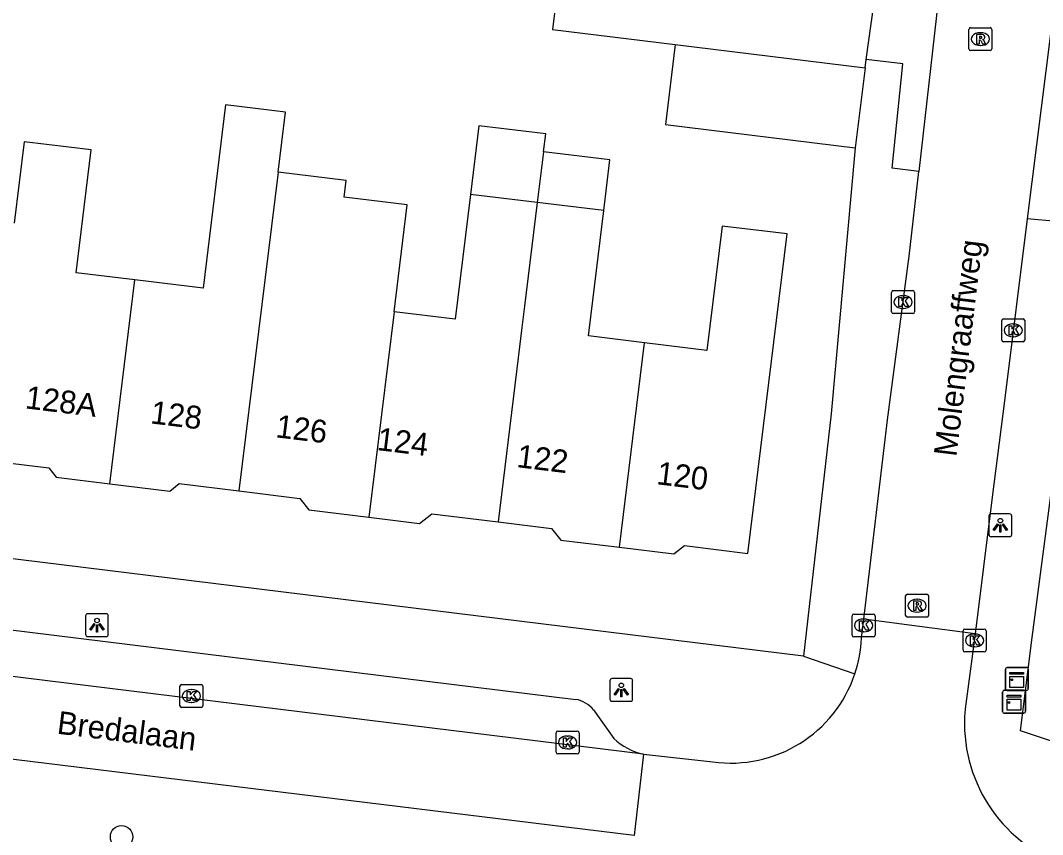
# Model space of a CAD drawing. Extents: x 158087 to 159494, y 382905 to 383981.
# Drawn here: x 158552.85 to 158597.49, y 383380.92 to 383416.5 of the extents above; entities that cross this region are included whole.
import ezdxf

# ---------------------------------------------------------------- set-up
doc = ezdxf.new("R2010")
doc.units = 0
for name, color, linetype in [('IMGEO_Boom', 7, 'Continuous'), ('IMGEO_Kast', 7, 'Continuous'), ('IMGEO_Kolk', 7, 'Continuous'), ('IMGEO_Lichtpunt', 7, 'Continuous'), ('IMGEO_Openbare_ruimte_label', 7, 'Continuous'), ('IMGEO_Pand', 7, 'Continuous'), ('IMGEO_Pand_nummerreeks', 7, 'Continuous'), ('IMGEO_Rijbaan_lokaal_gesloten', 7, 'Continuous'), ('IMGEO_Rijbaan_lokaal_open', 7, 'Continuous'), ('IMGEO_Rioolput', 7, 'Continuous'), ('IMGEO_Voetpad_open', 7, 'Continuous')]:
    doc.layers.add(name, color=color, linetype=linetype)

msp = doc.modelspace()

# ---------------------------------------------------------------- linework, layer by layer
at = {"layer": 'IMGEO_Boom'}
msp.add_circle((158557.267, 383380.82), 0.489, dxfattribs=at)
at = {"layer": 'IMGEO_Kast'}
for p, q in [((158595.872, 383387.295), (158595.872, 383388.136)), ((158595.872, 383388.136), (158595.872, 383387.295)), ((158595.947, 383388.22), (158596.788, 383388.22)), ((158596.788, 383388.22), (158595.947, 383388.22)), ((158596.872, 383388.145), (158596.872, 383387.304)), ((158596.872, 383387.304), (158596.872, 383388.145)), ((158595.749, 383386.302), (158595.749, 383387.143)), ((158595.749, 383387.143), (158595.749, 383386.302)), ((158595.824, 383387.227), (158596.665, 383387.227)), ((158596.665, 383387.227), (158595.824, 383387.227)), ((158596.797, 383387.22), (158595.956, 383387.22)), ((158595.956, 383387.22), (158596.797, 383387.22)), ((158596.749, 383387.152), (158596.749, 383386.311)), ((158596.749, 383386.311), (158596.749, 383387.152)), ((158596.674, 383386.227), (158595.833, 383386.227)), ((158595.833, 383386.227), (158596.674, 383386.227))]:
    msp.add_line(p, q, dxfattribs=at)
for points in [[(158596.067, 383388.01), (158596.667, 383388.01), (158596.667, 383387.925), (158596.067, 383387.925), (158596.067, 383388.01)], [(158596.067, 383387.835), (158596.667, 383387.835), (158596.667, 383387.346), (158596.067, 383387.346), (158596.067, 383387.835)], [(158595.944, 383387.017), (158596.544, 383387.017), (158596.544, 383386.932), (158595.944, 383386.932), (158595.944, 383387.017)], [(158595.944, 383386.842), (158596.544, 383386.842), (158596.544, 383386.353), (158595.944, 383386.353), (158595.944, 383386.842)]]:
    msp.add_lwpolyline(points, dxfattribs=at)
for centre in [(158596.151, 383387.684), (158596.028, 383386.691)]:
    msp.add_circle(centre, 0.0377, dxfattribs=at)
for centre, start, end in [((158595.95, 383388.142), 92.4484, 184.2845), ((158595.95, 383388.142), 92.4484, 184.2845), ((158596.794, 383388.142), 2.4484, 94.2845), ((158596.794, 383388.142), 2.4484, 94.2845), ((158595.827, 383387.149), 92.4484, 184.2845), ((158595.827, 383387.149), 92.4484, 184.2845), ((158595.95, 383387.298), 182.4484, 274.2845), ((158595.95, 383387.298), 182.4484, 274.2845), ((158596.671, 383387.149), 2.4484, 94.2845), ((158596.671, 383387.149), 2.4484, 94.2845), ((158596.794, 383387.298), 272.4484, 4.2845), ((158596.794, 383387.298), 272.4484, 4.2845), ((158595.827, 383386.305), 182.4484, 274.2845), ((158595.827, 383386.305), 182.4484, 274.2845), ((158596.671, 383386.305), 272.4484, 4.2845), ((158596.671, 383386.305), 272.4484, 4.2845)]:
    msp.add_arc(centre, 0.0779, start, end, dxfattribs=at)
at = {"layer": 'IMGEO_Kolk'}
for p, q in [((158590.901, 383403.766), (158590.901, 383404.618)), ((158590.976, 383404.692), (158591.828, 383404.692)), ((158591.389, 383404.472), (158591.414, 383404.472)), ((158591.902, 383404.618), (158591.902, 383403.766)), ((158591.412, 383403.912), (158591.387, 383403.912)), ((158591.828, 383403.692), (158590.976, 383403.692)), ((158595.789, 383403.459), (158596.641, 383403.459)), ((158595.714, 383402.533), (158595.714, 383403.385)), ((158596.202, 383403.239), (158596.227, 383403.239)), ((158596.715, 383403.385), (158596.715, 383402.533)), ((158596.225, 383402.679), (158596.2, 383402.679)), ((158596.641, 383402.459), (158595.789, 383402.459)), ((158589.177, 383389.633), (158589.177, 383390.485)), ((158589.252, 383390.559), (158590.104, 383390.559)), ((158590.178, 383390.485), (158590.178, 383389.633)), ((158589.665, 383390.339), (158589.69, 383390.339)), ((158589.688, 383389.779), (158589.663, 383389.779)), ((158594.024, 383388.977), (158594.024, 383389.829)), ((158594.099, 383389.903), (158594.951, 383389.903)), ((158594.512, 383389.683), (158594.537, 383389.683)), ((158595.025, 383389.829), (158595.025, 383388.977)), ((158590.104, 383389.559), (158589.252, 383389.559)), ((158594.951, 383388.903), (158594.099, 383388.903)), ((158594.535, 383389.123), (158594.51, 383389.123)), ((158559.817, 383386.548), (158559.817, 383387.4)), ((158559.892, 383387.474), (158560.744, 383387.474)), ((158560.818, 383387.4), (158560.818, 383386.548)), ((158560.305, 383387.254), (158560.33, 383387.254)), ((158560.744, 383386.474), (158559.892, 383386.474)), ((158560.328, 383386.694), (158560.303, 383386.694)), ((158576.247, 383384.518), (158576.247, 383385.37)), ((158576.322, 383385.444), (158577.174, 383385.444)), ((158576.735, 383385.224), (158576.76, 383385.224)), ((158577.248, 383385.37), (158577.248, 383384.518)), ((158577.174, 383384.444), (158576.322, 383384.444)), ((158576.758, 383384.664), (158576.733, 383384.664))]:
    msp.add_line(p, q, dxfattribs=at)
for points in [[(158590.901, 383403.766), (158590.901, 383404.618)], [(158590.976, 383404.692), (158591.828, 383404.692)], [(158591.222, 383404.392), (158591.345, 383404.392), (158591.345, 383404.241), (158591.475, 383404.392), (158591.639, 383404.392), (158591.493, 383404.241), (158591.646, 383403.992), (158591.494, 383403.992), (158591.409, 383404.156), (158591.345, 383404.089), (158591.345, 383403.992), (158591.222, 383403.992), (158591.222, 383404.392)], [(158591.902, 383404.618), (158591.902, 383403.766)], [(158591.828, 383403.692), (158590.976, 383403.692)], [(158595.789, 383403.459), (158596.641, 383403.459)], [(158595.714, 383402.533), (158595.714, 383403.385)], [(158596.035, 383403.159), (158596.158, 383403.159), (158596.158, 383403.008), (158596.288, 383403.159), (158596.452, 383403.159), (158596.306, 383403.008), (158596.459, 383402.759), (158596.307, 383402.759), (158596.222, 383402.923), (158596.158, 383402.856), (158596.158, 383402.759), (158596.035, 383402.759), (158596.035, 383403.159)], [(158596.715, 383403.385), (158596.715, 383402.533)], [(158596.641, 383402.459), (158595.789, 383402.459)], [(158589.177, 383389.633), (158589.177, 383390.485)], [(158589.252, 383390.559), (158590.104, 383390.559)], [(158590.178, 383390.485), (158590.178, 383389.633)], [(158589.498, 383390.259), (158589.621, 383390.259), (158589.621, 383390.108), (158589.751, 383390.259), (158589.915, 383390.259), (158589.769, 383390.108), (158589.922, 383389.859), (158589.77, 383389.859), (158589.685, 383390.023), (158589.621, 383389.956), (158589.621, 383389.859), (158589.498, 383389.859), (158589.498, 383390.259)], [(158594.024, 383388.977), (158594.024, 383389.829)], [(158594.099, 383389.903), (158594.951, 383389.903)], [(158594.345, 383389.603), (158594.468, 383389.603), (158594.468, 383389.452), (158594.598, 383389.603), (158594.762, 383389.603), (158594.616, 383389.452), (158594.769, 383389.203), (158594.617, 383389.203), (158594.532, 383389.367), (158594.468, 383389.3), (158594.468, 383389.203), (158594.345, 383389.203), (158594.345, 383389.603)], [(158595.025, 383389.829), (158595.025, 383388.977)], [(158590.104, 383389.559), (158589.252, 383389.559)], [(158594.951, 383388.903), (158594.099, 383388.903)], [(158559.817, 383386.548), (158559.817, 383387.4)], [(158559.892, 383387.474), (158560.744, 383387.474)], [(158560.818, 383387.4), (158560.818, 383386.548)], [(158560.138, 383387.174), (158560.261, 383387.174), (158560.261, 383387.023), (158560.391, 383387.174), (158560.555, 383387.174), (158560.409, 383387.023), (158560.562, 383386.774), (158560.41, 383386.774), (158560.325, 383386.938), (158560.261, 383386.871), (158560.261, 383386.774), (158560.138, 383386.774), (158560.138, 383387.174)], [(158560.744, 383386.474), (158559.892, 383386.474)], [(158576.247, 383384.518), (158576.247, 383385.37)], [(158576.322, 383385.444), (158577.174, 383385.444)], [(158576.568, 383385.144), (158576.691, 383385.144), (158576.691, 383384.993), (158576.821, 383385.144), (158576.985, 383385.144), (158576.839, 383384.993), (158576.992, 383384.744), (158576.84, 383384.744), (158576.755, 383384.908), (158576.691, 383384.841), (158576.691, 383384.744), (158576.568, 383384.744), (158576.568, 383385.144)], [(158577.248, 383385.37), (158577.248, 383384.518)], [(158577.174, 383384.444), (158576.322, 383384.444)]]:
    msp.add_lwpolyline(points, dxfattribs=at)
for centre, start, end in [((158590.978, 383404.616), 91.552, 178.448), ((158590.978, 383404.616), 91.552, 178.448), ((158591.826, 383404.616), 1.552, 88.448), ((158591.826, 383404.616), 1.552, 88.448), ((158590.978, 383403.768), 181.552, 268.448), ((158590.978, 383403.768), 181.552, 268.448), ((158591.826, 383403.768), 271.552, 358.448), ((158591.826, 383403.768), 271.552, 358.448), ((158595.791, 383403.383), 91.552, 178.448), ((158595.791, 383403.383), 91.552, 178.448), ((158596.639, 383403.383), 1.552, 88.448), ((158596.639, 383403.383), 1.552, 88.448), ((158595.791, 383402.535), 181.552, 268.448), ((158595.791, 383402.535), 181.552, 268.448), ((158596.639, 383402.535), 271.552, 358.448), ((158596.639, 383402.535), 271.552, 358.448), ((158589.254, 383390.483), 91.552, 178.448), ((158589.254, 383390.483), 91.552, 178.448), ((158590.102, 383390.483), 1.552, 88.448), ((158590.102, 383390.483), 1.552, 88.448), ((158589.254, 383389.635), 181.552, 268.448), ((158589.254, 383389.635), 181.552, 268.448), ((158590.102, 383389.635), 271.552, 358.448), ((158590.102, 383389.635), 271.552, 358.448), ((158594.101, 383389.827), 91.552, 178.448), ((158594.101, 383389.827), 91.552, 178.448), ((158594.949, 383389.827), 1.552, 88.448), ((158594.949, 383389.827), 1.552, 88.448), ((158594.101, 383388.979), 181.552, 268.448), ((158594.101, 383388.979), 181.552, 268.448), ((158594.949, 383388.979), 271.552, 358.448), ((158594.949, 383388.979), 271.552, 358.448), ((158559.894, 383387.398), 91.552, 178.448), ((158559.894, 383387.398), 91.552, 178.448), ((158560.742, 383387.398), 1.552, 88.448), ((158560.742, 383387.398), 1.552, 88.448), ((158559.894, 383386.55), 181.552, 268.448), ((158559.894, 383386.55), 181.552, 268.448), ((158560.742, 383386.55), 271.552, 358.448), ((158560.742, 383386.55), 271.552, 358.448), ((158576.324, 383385.368), 91.552, 178.448), ((158576.324, 383385.368), 91.552, 178.448), ((158577.172, 383385.368), 1.552, 88.448), ((158577.172, 383385.368), 1.552, 88.448), ((158576.324, 383384.52), 181.552, 268.448), ((158576.324, 383384.52), 181.552, 268.448), ((158577.172, 383384.52), 271.552, 358.448), ((158577.172, 383384.52), 271.552, 358.448)]:
    msp.add_arc(centre, 0.0765, start, end, dxfattribs=at)
for centre, major_axis, ratio, start_param, end_param in [((158591.388, 383404.192), (-0.387, 0.002), 0.722429, 4.712389, 7.853982), ((158591.413, 383404.192), (-0.39, 0.002), 0.717154, 1.570796, 4.712389), ((158596.201, 383402.959), (-0.387, 0.002), 0.722429, 4.712389, 7.853982), ((158596.226, 383402.959), (-0.39, 0.002), 0.717154, 1.570796, 4.712389), ((158589.664, 383390.059), (-0.387, 0.002), 0.722429, 4.712389, 7.853982), ((158589.689, 383390.059), (-0.39, 0.002), 0.717154, 1.570796, 4.712389), ((158594.511, 383389.403), (-0.387, 0.002), 0.722429, 4.712389, 7.853982), ((158594.536, 383389.403), (-0.39, 0.002), 0.717154, 1.570796, 4.712389), ((158560.304, 383386.974), (-0.387, 0.002), 0.722429, 4.712389, 7.853982), ((158560.329, 383386.974), (-0.39, 0.002), 0.717154, 1.570796, 4.712389), ((158576.734, 383384.944), (-0.387, 0.002), 0.722429, 4.712389, 7.853982), ((158576.759, 383384.944), (-0.39, 0.002), 0.717154, 1.570796, 4.712389)]:
    msp.add_ellipse(centre, major_axis=major_axis, ratio=ratio, start_param=start_param, end_param=end_param, dxfattribs=at)
at = {"layer": 'IMGEO_Lichtpunt'}
for p, q in [((158595.155, 383394.841), (158595.155, 383394.034)), ((158595.155, 383394.841), (158595.155, 383394.034)), ((158596.057, 383394.936), (158595.249, 383394.936)), ((158596.057, 383394.936), (158595.249, 383394.936)), ((158596.151, 383394.034), (158596.151, 383394.841)), ((158596.151, 383394.034), (158596.151, 383394.841)), ((158595.249, 383393.94), (158596.057, 383393.94)), ((158595.249, 383393.94), (158596.057, 383393.94)), ((158555.693, 383390.475), (158555.693, 383389.668)), ((158555.693, 383390.475), (158555.693, 383389.668)), ((158556.595, 383390.57), (158555.787, 383390.57)), ((158556.595, 383390.57), (158555.787, 383390.57)), ((158556.689, 383389.668), (158556.689, 383390.475)), ((158556.689, 383389.668), (158556.689, 383390.475)), ((158555.787, 383389.574), (158556.595, 383389.574)), ((158555.787, 383389.574), (158556.595, 383389.574)), ((158578.595, 383387.645), (158578.595, 383386.838)), ((158578.595, 383387.645), (158578.595, 383386.838)), ((158579.497, 383387.74), (158578.689, 383387.74)), ((158579.497, 383387.74), (158578.689, 383387.74)), ((158579.591, 383386.838), (158579.591, 383387.645)), ((158579.591, 383386.838), (158579.591, 383387.645)), ((158578.689, 383386.744), (158579.497, 383386.744)), ((158578.689, 383386.744), (158579.497, 383386.744))]:
    msp.add_line(p, q, dxfattribs=at)
for points in [[(158595.529, 383394.505), (158595.568, 383394.477), (158595.38, 383394.215), (158595.342, 383394.242), (158595.529, 383394.505)], [(158595.741, 383394.477), (158595.779, 383394.504), (158595.966, 383394.242), (158595.927, 383394.214), (158595.741, 383394.477)], [(158595.631, 383394.457), (158595.678, 383394.457), (158595.678, 383394.135), (158595.631, 383394.135), (158595.631, 383394.457)], [(158556.067, 383390.139), (158556.106, 383390.111), (158555.918, 383389.849), (158555.88, 383389.876), (158556.067, 383390.139)], [(158556.169, 383390.091), (158556.216, 383390.091), (158556.216, 383389.769), (158556.169, 383389.769), (158556.169, 383390.091)], [(158556.279, 383390.111), (158556.317, 383390.138), (158556.504, 383389.876), (158556.465, 383389.848), (158556.279, 383390.111)], [(158578.969, 383387.309), (158579.008, 383387.281), (158578.82, 383387.019), (158578.782, 383387.046), (158578.969, 383387.309)], [(158579.071, 383387.261), (158579.118, 383387.261), (158579.118, 383386.939), (158579.071, 383386.939), (158579.071, 383387.261)], [(158579.181, 383387.281), (158579.219, 383387.308), (158579.406, 383387.046), (158579.367, 383387.018), (158579.181, 383387.281)]]:
    msp.add_lwpolyline(points, dxfattribs=at)
for centre in [(158595.654, 383394.639), (158556.192, 383390.273), (158579.094, 383387.443)]:
    msp.add_circle(centre, 0.0994, dxfattribs=at)
for centre, start, end in [((158595.249, 383394.841), 90, 180), ((158595.249, 383394.841), 90, 180), ((158596.057, 383394.841), 0, 90), ((158596.057, 383394.841), 0, 90), ((158595.249, 383394.034), 180, 270), ((158595.249, 383394.034), 180, 270), ((158596.057, 383394.034), 270, 0), ((158596.057, 383394.034), 270, 360), ((158555.787, 383390.475), 90, 180), ((158555.787, 383390.475), 90, 180), ((158556.595, 383390.475), 0, 90), ((158556.595, 383390.475), 0, 90), ((158555.787, 383389.668), 180, 270), ((158555.787, 383389.668), 180, 270), ((158556.595, 383389.668), 270, 0), ((158556.595, 383389.668), 270, 360), ((158578.689, 383387.645), 90, 180), ((158578.689, 383387.645), 90, 180), ((158579.497, 383387.645), 0, 90), ((158579.497, 383387.645), 0, 90), ((158578.689, 383386.838), 180, 270), ((158578.689, 383386.838), 180, 270), ((158579.497, 383386.838), 270, 0), ((158579.497, 383386.838), 270, 360)]:
    msp.add_arc(centre, 0.0946, start, end, dxfattribs=at)
at = {"layer": 'IMGEO_Pand'}
for points in [[(158581.45, 383415.451), (158581.02, 383411.95), (158589.317, 383410.932)], [(158581.45, 383415.451), (158589.746, 383414.433)], [(158589.746, 383414.433), (158589.317, 383410.932)], [(158564.103, 383409.864), (158564.426, 383412.496), (158561.813, 383412.816), (158560.832, 383404.795), (158557.853, 383405.16)], [(158575.697, 383410.759), (158575.793, 383411.542), (158572.868, 383411.9), (158572.501, 383408.901)], [(158557.853, 383405.16), (158555.285, 383405.475), (158555.94, 383410.842), (158553.008, 383411.2), (158552.574, 383407.648)], [(158575.697, 383410.759), (158575.425, 383408.544)], [(158578.33, 383408.189), (158578.601, 383410.403), (158575.697, 383410.759)], [(158564.103, 383409.864), (158562.395, 383395.936)], [(158569.173, 383403.772), (158569.746, 383408.437), (158566.986, 383408.774), (158567.076, 383409.501), (158564.103, 383409.864)], [(158572.501, 383408.901), (158571.834, 383403.446), (158569.173, 383403.772)], [(158575.425, 383408.544), (158572.501, 383408.901)], [(158575.425, 383408.544), (158574.869, 383404.011), (158574.756, 383403.088), (158574.593, 383401.76), (158573.714, 383394.589)], [(158578.33, 383408.189), (158575.425, 383408.544)], [(158580.112, 383402.416), (158577.658, 383402.715), (158577.76, 383403.547), (158578.33, 383408.189)], [(158579.015, 383393.475), (158581.387, 383393.184), (158581.851, 383393.547), (158584.626, 383393.207), (158586.107, 383405.277), (158586.339, 383407.17), (158583.5, 383407.517), (158582.836, 383402.083), (158580.112, 383402.416)], [(158556.76, 383396.25), (158557.853, 383405.16)], [(158569.173, 383403.772), (158568.071, 383394.79)], [(158579.015, 383393.475), (158580.112, 383402.416)], [(158551.317, 383397.287), (158554.086, 383396.948), (158554.406, 383396.538), (158556.76, 383396.25)], [(158556.76, 383396.25), (158559.371, 383395.93), (158559.788, 383396.256), (158562.395, 383395.936)], [(158562.395, 383395.936), (158565.054, 383395.61), (158565.443, 383395.113), (158568.071, 383394.79)], [(158568.071, 383394.79), (158570.275, 383394.52), (158570.817, 383394.944), (158573.714, 383394.589)], [(158573.714, 383394.589), (158576.049, 383394.302), (158576.449, 383393.79), (158579.015, 383393.475)]]:
    msp.add_lwpolyline(points, dxfattribs=at)
at = {"layer": 'IMGEO_Rijbaan_lokaal_gesloten'}
for points in [[(158580.062, 383384.432), (158538.992, 383389.488), (158465.723, 383398.507)], [(158579.65, 383380.875), (158538.64, 383385.899), (158510.146, 383389.39)]]:
    msp.add_lwpolyline(points, dxfattribs=at)
at = {"layer": 'IMGEO_Rijbaan_lokaal_open'}
for points in [[(158593.034, 383418.281), (158592.085, 383409.901)], [(158597.837, 383415.923), (158596.823, 383407.828)], [(158589.693, 383390.333), (158590.729, 383399.039), (158591.666, 383406.2), (158592.085, 383409.901)], [(158596.823, 383407.828), (158595.841, 383399.988), (158595.278, 383395.555), (158594.558, 383389.694)], [(158589.588, 383389.499), (158589.693, 383390.333)], [(158594.558, 383389.694), (158589.693, 383390.333)], [(158594.558, 383389.694), (158594.117, 383386.408), (158594.111, 383386.349), (158594.106, 383386.29)], [(158580.062, 383384.432), (158579.65, 383380.875)], [(158580.062, 383384.432), (158583.088, 383384.097)]]:
    msp.add_lwpolyline(points, dxfattribs=at)
for centre, radius, start, end in [((158583.943, 383389.747), 5.65, 341.4208, 357.4826), ((158583.877, 383389.759), 5.716, 262.0643, 341.5226), ((158600.649, 383385.773), 6.563, 175.4863, 249.953)]:
    msp.add_arc(centre, radius, start, end, dxfattribs=at)
at = {"layer": 'IMGEO_Rioolput'}
for p, q in [((158594.277, 383415.259), (158594.277, 383416.111)), ((158594.352, 383416.185), (158595.204, 383416.185)), ((158594.765, 383415.965), (158594.79, 383415.965)), ((158595.278, 383416.111), (158595.278, 383415.259)), ((158595.204, 383415.185), (158594.352, 383415.185)), ((158594.788, 383415.405), (158594.763, 383415.405)), ((158591.589, 383391.422), (158592.441, 383391.422)), ((158591.514, 383390.496), (158591.514, 383391.348)), ((158592.002, 383391.202), (158592.027, 383391.202)), ((158592.515, 383391.348), (158592.515, 383390.496)), ((158592.025, 383390.642), (158592, 383390.642)), ((158592.441, 383390.422), (158591.589, 383390.422))]:
    msp.add_line(p, q, dxfattribs=at)
for points in [[(158594.277, 383415.259), (158594.277, 383416.111)], [(158594.352, 383416.185), (158595.204, 383416.185)], [(158595.278, 383416.111), (158595.278, 383415.259)], [(158594.866, 383415.883), (158594.614, 383415.885), (158594.614, 383415.485)], [(158594.614, 383415.485), (158594.738, 383415.485), (158594.738, 383415.647), (158594.749, 383415.647)], [(158594.792, 383415.804), (158594.738, 383415.804), (158594.738, 383415.723)], [(158594.738, 383415.723), (158594.79, 383415.723)], [(158594.796, 383415.618), (158594.867, 383415.485), (158595.007, 383415.485), (158594.942, 383415.611)], [(158595.204, 383415.185), (158594.352, 383415.185)], [(158591.589, 383391.422), (158592.441, 383391.422)], [(158591.514, 383390.496), (158591.514, 383391.348)], [(158592.103, 383391.12), (158591.851, 383391.122), (158591.851, 383390.722)], [(158592.029, 383391.041), (158591.975, 383391.041), (158591.975, 383390.96)], [(158591.975, 383390.96), (158592.027, 383390.96)], [(158592.515, 383391.348), (158592.515, 383390.496)], [(158591.851, 383390.722), (158591.975, 383390.722), (158591.975, 383390.884), (158591.986, 383390.884)], [(158592.033, 383390.855), (158592.104, 383390.722), (158592.244, 383390.722), (158592.179, 383390.848)], [(158592.441, 383390.422), (158591.589, 383390.422)]]:
    msp.add_lwpolyline(points, dxfattribs=at)
for centre, radius, start, end in [((158594.354, 383416.109), 0.0765, 91.552, 178.448), ((158594.354, 383416.109), 0.0765, 91.552, 178.448), ((158595.202, 383416.109), 0.0765, 1.552, 88.448), ((158595.202, 383416.109), 0.0765, 1.552, 88.448), ((158594.748, 383415.594), 0.0533, 26.0293, 88.6989), ((158594.774, 383415.912), 0.19, 274.7715, 282.9687), ((158594.798, 383415.708), 0.0964, 77.0061, 93.1865), ((158594.812, 383415.765), 0.0378, 276.6634, 79.6772), ((158594.865, 383415.773), 0.109, 350.3612, 89.416), ((158594.863, 383415.773), 0.112, 277.5842, 350.9817), ((158594.847, 383415.558), 0.108, 29.5134, 73.7905), ((158594.354, 383415.261), 0.0765, 181.552, 268.448), ((158594.354, 383415.261), 0.0765, 181.552, 268.448), ((158595.202, 383415.261), 0.0765, 271.552, 358.448), ((158595.202, 383415.261), 0.0765, 271.552, 358.448), ((158591.591, 383391.346), 0.0765, 91.552, 178.448), ((158591.591, 383391.346), 0.0765, 91.552, 178.448), ((158592.439, 383391.346), 0.0765, 1.552, 88.448), ((158592.439, 383391.346), 0.0765, 1.552, 88.448), ((158592.011, 383391.149), 0.19, 274.7715, 282.9687), ((158592.035, 383390.945), 0.0964, 77.0061, 93.1865), ((158592.049, 383391.002), 0.0378, 276.6634, 79.6772), ((158592.102, 383391.01), 0.109, 350.3612, 89.416), ((158592.1, 383391.01), 0.112, 277.5842, 350.9817), ((158591.591, 383390.498), 0.0765, 181.552, 268.448), ((158591.591, 383390.498), 0.0765, 181.552, 268.448), ((158591.985, 383390.831), 0.0533, 26.0293, 88.6989), ((158592.084, 383390.795), 0.108, 29.5134, 73.7905), ((158592.439, 383390.498), 0.0765, 271.552, 358.448), ((158592.439, 383390.498), 0.0765, 271.552, 358.448)]:
    msp.add_arc(centre, radius, start, end, dxfattribs=at)
for centre, major_axis, ratio, start_param, end_param in [((158594.764, 383415.685), (-0.387, 0.002), 0.722429, 4.712389, 7.853982), ((158594.789, 383415.685), (-0.39, 0.002), 0.717154, 1.570796, 4.712389), ((158592.001, 383390.922), (-0.387, 0.002), 0.722429, 4.712389, 7.853982), ((158592.026, 383390.922), (-0.39, 0.002), 0.717154, 1.570796, 4.712389)]:
    msp.add_ellipse(centre, major_axis=major_axis, ratio=ratio, start_param=start_param, end_param=end_param, dxfattribs=at)
at = {"layer": 'IMGEO_Voetpad_open'}
for points in [[(158558.354, 383419.651), (158576.266, 383417.538), (158576.097, 383416.108), (158581.45, 383415.451)], [(158589.795, 383414.791), (158590.222, 383417.921)], [(158589.746, 383414.433), (158589.795, 383414.791)], [(158592.085, 383409.901), (158590.93, 383410.046), (158591.391, 383414.607), (158589.795, 383414.791)], [(158589.317, 383410.932), (158588.261, 383399.307), (158587.052, 383388.722)], [(158717.275, 383344.991), (158632.176, 383373.566), (158596.53, 383385.454), (158596.995, 383389.197), (158599.411, 383407.598)], [(158599.411, 383407.598), (158596.823, 383407.828)], [(158469.214, 383400.114), (158510.534, 383395.003), (158515.06, 383394.465), (158539.189, 383391.495), (158577.108, 383386.827)], [(158587.052, 383388.722), (158539.491, 383394.575), (158512.098, 383397.946)], [(158587.052, 383388.722), (158589.299, 383387.947)], [(158577.883, 383386.366), (158578.762, 383385.12)]]:
    msp.add_lwpolyline(points, dxfattribs=at)
for centre, radius, start, end in [((158576.885, 383385.571), 1.276, 38.5605, 79.9478), ((158580.657, 383387.128), 2.76, 226.66, 257.5616)]:
    msp.add_arc(centre, radius, start, end, dxfattribs=at)

# ---------------------------------------------------------------- texts
at = {"layer": 'IMGEO_Openbare_ruimte_label'}
for s, rotation, p in [('Molengraaffweg', 83.0526, (158593.732, 383397.407)), ('Bredalaan', 352.9319, (158554.415, 383385.333))]:
    msp.add_text(s, height=1, rotation=rotation, dxfattribs=at).set_placement(p)
at = {"layer": 'IMGEO_Pand_nummerreeks'}
for s, rotation, p in [('128A', 353.0416, (158553.025, 383399.55)), ('128', 353.0416, (158558.497, 383398.894)), ('126', 353.0416, (158563.969, 383398.286)), ('124', 353.0443, (158568.389, 383397.728)), ('122', 353.0443, (158574.493, 383396.982)), ('120', 353.0416, (158580.604, 383396.236))]:
    msp.add_text(s, height=1, rotation=rotation, dxfattribs=at).set_placement(p)

doc.saveas('drawing.dxf')
